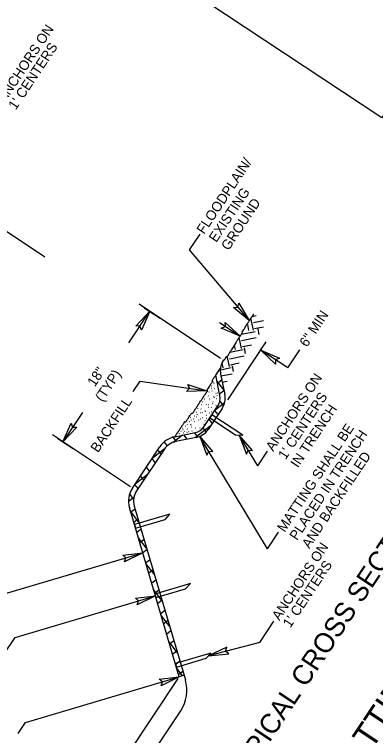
# Model space of a CAD drawing. Extents: x 561231 to 564240, y 590260 to 602519.
# Drawn here: x 563598.7 to 563838.5, y 590578.6 to 591057.7 of the extents above; entities that cross this region are included whole.
import ezdxf

# ---------------------------------------------------------------- set-up
doc = ezdxf.new("R2010")
doc.units = 0
doc.layers.add('Old_Level_1', color=7, linetype='Continuous')
doc.layers.add('Old_Level_2', color=7, linetype='Continuous')

# ---------------------------------------------------------------- blocks, each defined once
blk = doc.blocks.new('TERM')
at = {"layer": 'Old_Level_2'}
blk.add_lwpolyline([(-27, 4.65), (0, 0), (-27.15, -4.8), (-23.7, 0)], close=True, dxfattribs=at)

msp = doc.modelspace()

# ---------------------------------------------------------------- linework, layer by layer
at = {"layer": 'Old_Level_1'}
for p, q in [((563550.87, 590941.95), (563618.87, 590896.77)), ((563721.7, 590911.65), (563714.78, 590901.25)), ((563714.78, 590901.25), (563754.56, 590854.33)), ((563735.57, 590829.21), (563681.52, 590865.12)), ((563674.64, 590839.61), (563688.51, 590860.48)), ((563684.95, 590862.85), (563695.51, 590855.83)), ((563684.95, 590862.85), (563691.24, 590858.67)), ((563757.33, 590847.87), (563755.72, 590855.86)), ((563756.54, 590857.11), (563759.29, 590857.66)), ((563734.84, 590852.94), (563748.48, 590843.88)), ((563754.38, 590847.67), (563753.58, 590851.64)), ((563757.32, 590853.09), (563764.11, 590854.46)), ((563758.14, 590849.09), (563763.98, 590850.25)), ((563749.41, 590845.31), (563758.61, 590847.16)), ((563761.2, 590845.05), (563760.42, 590848.89)), ((563749.41, 590835.83), (563747.94, 590843.1)), ((563749.38, 590841.14), (563759.24, 590843.12)), ((563740.39, 590801.7), (563765.93, 590840.13)), ((563743.2, 590835.4), (563745.92, 590839.49)), ((563745.39, 590835.02), (563744.82, 590837.84)), ((563750.19, 590837.12), (563756.05, 590838.3)), ((563752.11, 590832.38), (563751.34, 590836.22)), ((563765.2, 590838.02), (563765.2, 590838.02)), ((563741.38, 590828.99), (563751.17, 590830.97)), ((563741.78, 590833.25), (563750.61, 590835.03)), ((563780.16, 590822.83), (563762.31, 590834.69)), ((563780.15, 590822.83), (563788.21, 590834.97)), ((563737.38, 590822.96), (563736.7, 590826.3)), ((563741.4, 590823.77), (563740.01, 590830.65)), ((563742.19, 590824.97), (563747.96, 590826.14)), ((563732.38, 590818.06), (563735.45, 590822.67)), ((563735.43, 590822.41), (563735.1, 590822.14)), ((563735.44, 590821.99), (563735.21, 590822.3)), ((563735.58, 590821.64), (563742.66, 590823.07)), ((563744.15, 590820.41), (563743.39, 590824.18)), ((563735.12, 590804.46), (563732.38, 590818.06)), ((563735.59, 590818.7), (563738.34, 590805.11)), ((563735.84, 590817.51), (563743.22, 590819)), ((563677.6, 590807.12), (563682.27, 590814.14)), ((563682.27, 590814.14), (563726.54, 590807.72)), ((563730.96, 590813.68), (563731.16, 590813.69)), ((563731.34, 590812.25), (563731.18, 590812.49)), ((563737.68, 590808.35), (563733.15, 590814.23)), ((563736.37, 590814.84), (563733.47, 590812.62)), ((563736.65, 590813.5), (563740.01, 590814.17)), ((563727.68, 590807.03), (563727.89, 590807.03)), ((563729.4, 590809.47), (563729.61, 590809.46)), ((563729.7, 590810.84), (563729.54, 590811.08)), ((563730.06, 590807.51), (563729.91, 590807.75)), ((563731.34, 590809.18), (563731.54, 590809.18)), ((563737.81, 590807.69), (563734.92, 590805.47)), ((563724.99, 590802.31), (563725.2, 590802.3)), ((563727.56, 590804.01), (563727.41, 590804.26)), ((563727.93, 590802.26), (563728.13, 590802.27)), ((563730.6, 590803.95), (563730.84, 590803.83)), ((563731.21, 590803.5), (563731.43, 590803.51)), ((563732.38, 590806.07), (563732.6, 590806.06)), ((563732.96, 590802.52), (563733.17, 590802.52)), ((563733.31, 590804.35), (563733.16, 590804.61)), ((563733.48, 590806.09), (563733.32, 590806.33)), ((563722.9, 590798.62), (563723.11, 590798.62)), ((563723.49, 590800.26), (563723.7, 590800.25)), ((563724.53, 590783.74), (563733.8, 590797.69)), ((563726.16, 590798.6), (563726.01, 590798.84)), ((563727.56, 590798.54), (563727.76, 590798.52)), ((563730.43, 590798.93), (563730.28, 590799.17)), ((563730.71, 590800.18), (563730.56, 590800.42)), ((563738.18, 590799.7), (563731.94, 590794.9)), ((563732.38, 590798.16), (563732.59, 590798.14)), ((563737.55, 590797.8), (563735.09, 590800.99)), ((563643.91, 590793.36), (563630.88, 590773.74)), ((563719.45, 590793.4), (563719.65, 590793.41)), ((563720.57, 590795.75), (563720.42, 590795.99)), ((563722.31, 590793.33), (563722.53, 590793.34)), ((563722.74, 590795.57), (563722.57, 590795.79)), ((563723.59, 590793.07), (563723.44, 590793.31)), ((563725.2, 590794.42), (563725.41, 590794.42)), ((563725.69, 590793.84), (563725.54, 590794.08)), ((563736.53, 590795.88), (563727.26, 590781.93)), ((563727.43, 590796.86), (563727.65, 590796.87)), ((563728.21, 590793.03), (563728.41, 590793.04)), ((563729.31, 590793.95), (563729.52, 590793.95)), ((563729.57, 590796.59), (563729.41, 590796.83)), ((563733.86, 590791.86), (563731.74, 590794.6)), ((563715.68, 590790.15), (563715.88, 590790.17)), ((563716.37, 590788.24), (563716.21, 590788.46)), ((563717.29, 590789.08), (563717.49, 590789.1)), ((563718.01, 590791.12), (563718.21, 590791.12)), ((563719.62, 590790.46), (563719.82, 590790.47)), ((563720.29, 590791.59), (563720.13, 590791.83)), ((563721.24, 590788.05), (563721.08, 590788.29)), ((563722.1, 590788.99), (563722.3, 590788.97)), ((563723.5, 590789.89), (563723.72, 590789.88)), ((563725.33, 590787.67), (563725.17, 590787.89)), ((563726.14, 590791.28), (563725.98, 590791.52)), ((563726.02, 590789.53), (563726.24, 590789.54)), ((563730.02, 590786.09), (563727.91, 590788.83)), ((563729.84, 590791.74), (563728.48, 590789.69)), ((563728.48, 590789.69), (563745.54, 590778.36)), ((563750.31, 590778.14), (563729.84, 590791.74)), ((563710.01, 590782.84), (563710.23, 590782.84)), ((563712.2, 590784.15), (563712.4, 590784.15)), ((563713.58, 590785.22), (563713.42, 590785.46)), ((563714.67, 590787.16), (563714.87, 590787.17)), ((563715.76, 590785.18), (563715.6, 590785.42)), ((563715.74, 590785.04), (563715.95, 590785.03)), ((563716.2, 590783.72), (563716.42, 590783.72)), ((563718.05, 590787.16), (563718.26, 590787.18)), ((563718.77, 590783.02), (563718.98, 590783.02)), ((563728.74, 590784.16), (563718.89, 590776.57)), ((563721.03, 590784.69), (563721.24, 590784.68)), ((563722.06, 590782.74), (563721.91, 590782.98)), ((563726.07, 590780.49), (563724.04, 590783.12)), ((563724.4, 590785.61), (563724.61, 590785.61)), ((563675.72, 590743.95), (563623.89, 590778.39)), ((563710.23, 590778.16), (563703.99, 590773.36)), ((563705.2, 590777.15), (563718.8, 590779.89)), ((563708.3, 590779.05), (563708.17, 590779.29)), ((563709.19, 590780.95), (563709.4, 590780.95)), ((563710.57, 590782.06), (563710.77, 590782.06)), ((563710.67, 590779.66), (563710.87, 590779.66)), ((563713.4, 590775.46), (563711.18, 590778.35)), ((563711.63, 590780.69), (563711.47, 590780.91)), ((563713.18, 590780.25), (563713.39, 590780.23)), ((563713.53, 590782.51), (563713.74, 590782.51)), ((563714.39, 590780.43), (563714.23, 590780.67)), ((563716.51, 590781.1), (563716.73, 590781.11)), ((563720.49, 590776.98), (563718.33, 590779.79)), ((563745.54, 590778.36), (563750.31, 590778.14)), ((563760.2, 590757.8), (563747.9, 590778.24)), ((563627.32, 590776.1), (563637.88, 590769.09)), ((563627.32, 590776.1), (563633.61, 590771.93)), ((563700.24, 590771.09), (563698.23, 590773.69)), ((563706.25, 590774.02), (563704.06, 590776.85)), ((563719.45, 590776.68), (563705.85, 590773.94)), ((563766.71, 590702.74), (563721.67, 590777.53)), ((563677.07, 590743.05), (563695.32, 590770.51)), ((563698.05, 590768.69), (563679.8, 590741.24)), ((563698.22, 590768.91), (563690.09, 590762.65)), ((563696.08, 590765.75), (563693.97, 590768.49)), ((563760.2, 590757.8), (563766.62, 590767.46)), ((563692.25, 590759.98), (563690.14, 590762.72)), ((563688.42, 590754.22), (563686.31, 590756.96)), ((563686.89, 590751.92), (563678.83, 590745.71)), ((563684.59, 590748.45), (563682.48, 590751.19)), ((563680.76, 590742.7), (563678.65, 590745.44)), ((563678, 590736.79), (563674.54, 590734.13)), ((563677.87, 590735.71), (563675.25, 590739.13)), ((563678.25, 590730.97), (563712.2, 590615.62)), ((563708.16, 590617.73), (563675.11, 590730.04)), ((563681.34, 590720.49), (563675.81, 590727.66)), ((563678.79, 590729.13), (563676.01, 590726.98)), ((563701.99, 590725.76), (563678.41, 590718.82)), ((563698.75, 590722.25), (563701.99, 590725.76)), ((563680.77, 590722.38), (563677.99, 590720.24)), ((563679.1, 590716.47), (563698.75, 590722.25)), ((563678.41, 590718.82), (563679.1, 590716.47)), ((563682.77, 590715.65), (563679.97, 590713.5)), ((563766.71, 590702.74), (563774.06, 590713.8)), ((563686.44, 590703.12), (563680.92, 590710.29)), ((563684.74, 590708.91), (563681.96, 590706.76)), ((563686.73, 590702.16), (563683.95, 590700.02)), ((563574.1, 590667.43), (563683.93, 590700.05)), ((563688.72, 590695.42), (563685.93, 590693.27)), ((563691.56, 590685.76), (563686.04, 590692.93)), ((563690.69, 590688.68), (563687.91, 590686.53)), ((563692.68, 590681.94), (563689.89, 590679.79)), ((563715.57, 590679.61), (563691.99, 590672.67)), ((563712.34, 590676.09), (563715.57, 590679.61)), ((563696.67, 590668.38), (563691.14, 590675.56)), ((563694.67, 590675.2), (563691.89, 590673.05)), ((563691.99, 590672.67), (563692.69, 590670.31)), ((563692.69, 590670.31), (563712.34, 590676.09)), ((563599.13, 590643.8), (563692.34, 590671.48)), ((563696.64, 590668.46), (563693.86, 590666.32)), ((563698.63, 590661.71), (563695.85, 590659.57)), ((563701.78, 590651.03), (563696.25, 590658.2)), ((563700.62, 590654.97), (563697.83, 590652.82)), ((563761.52, 590640.48), (563770.89, 590654.58)), ((563702.61, 590648.23), (563699.81, 590646.08)), ((563591.48, 590632.28), (563599.13, 590643.8)), ((563706.89, 590633.65), (563701.36, 590640.82)), ((563704.58, 590641.5), (563701.79, 590639.34)), ((563761.52, 590640.48), (563727.54, 590631.69)), ((563706.57, 590634.75), (563703.79, 590632.6)), ((563729.16, 590633.45), (563705.58, 590626.51)), ((563706.27, 590624.15), (563725.92, 590629.94)), ((563725.92, 590629.94), (563729.16, 590633.45)), ((563705.58, 590626.51), (563706.27, 590624.15)), ((563708.56, 590628), (563705.78, 590625.86)), ((563710.39, 590618.39), (563706.47, 590623.47)), ((563710.53, 590621.26), (563707.75, 590619.12)), ((563605.97, 590587.38), (563708.16, 590617.73)), ((563645.21, 590522.98), (563707.36, 590616.53)), ((563711.29, 590618.65), (563708.16, 590617.73)), ((563712, 590616.29), (563711.99, 590616.3)), ((563656.3, 590515.62), (563709.09, 590595.08)), ((563601.13, 590580.09), (563605.97, 590587.38))]:
    msp.add_line(p, q, dxfattribs=at)
for points in [[(563700.37, 591083.36), (563785.96, 591212.17), (563928.11, 591117.72), (563842.52, 590988.91)], [(563679.26, 590850.7), (563688.51, 590860.48), (563683.09, 590848.06), (563682.07, 590850.78)], [(563738.69, 590853.12), (563748.48, 590843.88), (563736.06, 590849.3), (563738.78, 590850.32)], [(563772.1, 590825.45), (563762.31, 590834.69), (563774.74, 590829.27), (563772.01, 590828.25)], [(563640.13, 590783.52), (563630.88, 590773.74), (563636.29, 590786.15), (563637.32, 590783.44)]]:
    msp.add_lwpolyline(points, close=True, dxfattribs=at)
for centre, radius, start, end in [((563748.61, 590820.78), 13.3, 147.4515, 171.833), ((563747.64, 590821.13), 12.29, 172.8174, 191.3993), ((563726.29, 590802.68), 9.01, 326.3993, 11.3993), ((563726.29, 590802.68), 12.29, 326.3993, 11.3993), ((563717.02, 590788.73), 9.01, 281.3993, 326.3993), ((563717.02, 590788.73), 12.29, 281.3993, 326.3993), ((563708.28, 590761.89), 15.57, 101.3993, 146.3993), ((563708.28, 590761.89), 12.29, 101.3993, 146.3993), ((563690.04, 590734.44), 15.57, 146.3993, 196.3993), ((563690.04, 590734.44), 12.29, 146.3993, 196.3993), ((563688.62, 590608.68), 24.58, 326.3993, 16.3993)]:
    msp.add_arc(centre, radius, start, end, dxfattribs=at)
for points in [[(563737.41, 590827.93), (563737.73, 590828.24), (563737.98, 590828.08), (563738.28, 590828.54), (563738.59, 590829), (563738.9, 590829.47), (563739.2, 590829.93), (563739.36, 590830.16), (563740.07, 590830.69), (563740.83, 590831.85), (563741.45, 590832.77), (563742.22, 590833.93), (563742.83, 590834.85), (563743.14, 590835.32), (563743.29, 590835.55), (563743.45, 590835.78), (563743.6, 590836.01), (563743.75, 590836.24), (563744.22, 590836.94), (563744.68, 590837.63), (563745.44, 590838.79), (563745.91, 590839.48), (563746.12, 590840.34), (563746.58, 590841.03), (563746.73, 590841.26), (563746.89, 590841.49), (563747.5, 590842.42), (563747.96, 590843.11), (563748.42, 590843.81), (563748.73, 590844.27), (563749.04, 590844.73), (563749.35, 590845.19), (563749.5, 590845.43), (563749.81, 590845.89), (563749.96, 590846.12), (563750.18, 590846.98), (563751.1, 590848.37), (563751.71, 590849.29), (563752.23, 590850.61), (563752.69, 590851.3), (563752.85, 590851.54), (563753.16, 590852), (563753.31, 590852.23), (563753.46, 590852.46), (563753.62, 590852.69), (563754.08, 590853.39), (563754.54, 590854.08), (563754.85, 590854.54), (563755.15, 590855.01), (563755.77, 590855.93), (563756.08, 590856.39), (563756.23, 590856.62), (563756.54, 590857.09), (563756.84, 590857.55), (563757.15, 590858.01), (563757.3, 590858.24), (563757.61, 590858.71)], [(563705.2, 590777.15), (563705.52, 590777.63), (563705.83, 590778.09), (563706.14, 590778.55), (563706.45, 590779.02), (563706.75, 590779.48), (563707.06, 590779.94), (563707.37, 590780.41), (563707.68, 590780.87), (563707.98, 590781.33), (563708.29, 590781.79), (563708.9, 590782.72), (563709.21, 590783.18), (563709.52, 590783.64), (563709.83, 590784.11), (563710.13, 590784.57), (563710.75, 590785.49), (563711.36, 590786.42), (563711.98, 590787.34), (563712.47, 590787.02), (563712.78, 590787.48), (563713.09, 590787.94), (563713.39, 590788.4), (563714.01, 590789.33), (563714.32, 590789.79), (563715.24, 590791.18), (563715.55, 590791.64), (563716.16, 590792.57), (563717.27, 590793.16), (563718.19, 590794.55), (563718.5, 590795.01), (563718.8, 590795.48), (563719.42, 590796.4), (563719.73, 590796.86), (563720.03, 590797.33), (563720.34, 590797.79), (563720.65, 590798.25), (563720.96, 590798.71), (563721.26, 590799.18), (563721.88, 590800.1), (563722.8, 590801.49), (563723.42, 590802.42), (563724.03, 590803.34), (563724.34, 590803.8), (563724.64, 590804.27), (563725.26, 590805.19), (563725.57, 590805.65), (563725.87, 590806.12), (563726.18, 590806.58), (563726.8, 590807.5), (563726.92, 590808.76), (563727.22, 590809.22), (563728.15, 590810.61), (563729.38, 590812.46), (563729.99, 590813.38), (563730.3, 590813.84), (563730.11, 590814.64), (563730.42, 590815.1), (563731.03, 590816.02), (563731.34, 590816.49), (563732.38, 590818.06)]]:
    msp.add_spline(points, degree=3, dxfattribs=at)

# ---------------------------------------------------------------- block references
for p, xscale, yscale, rotation in [((563754.55, 590854.34), 0.4913280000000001, 0.49132800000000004, -49.711969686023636), ((563726.55, 590807.72), 0.49132800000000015, 0.49132800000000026, -8.256239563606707), ((563721.69, 590777.54), 0.4913280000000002, -0.4913280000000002, 121.05520550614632), ((563747.92, 590778.25), 0.4913280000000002, -0.4913280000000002, 121.05520550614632), ((563683.94, 590700.06), 0.49132800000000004, 0.49132800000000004, 16.53992181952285), ((563692.35, 590671.49), 0.49132800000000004, 0.49132800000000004, 16.53992181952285), ((563727.54, 590631.69), 0.491328, -0.49132800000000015, -164.96308296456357), ((563708.17, 590617.74), 0.49132800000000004, 0.49132800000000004, 16.53992181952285)]:
    msp.add_blockref('TERM', p, dxfattribs=dict(at, xscale=xscale, yscale=yscale, rotation=rotation))

# ---------------------------------------------------------------- texts
for s, height, rotation, p in [('ANCHORS ON', 6.551, 56.3993, (563592.3, 590998.67)), ("1' CENTERS", 6.551, 56.3993, (563599.6, 590993.83)), ('FLOODPLAIN/', 6.5511, 56.3993, (563724.55, 590911.26)), ('EXISTING', 6.551, 56.3993, (563732.73, 590905.82)), ('GROUND', 6.551, 56.3993, (563740.92, 590900.38)), ('6" MIN', 6.551, 56.3993, (563792.89, 590836.22)), ('18"', 6.551, 56.3995, (563652.05, 590809.87)), ('(TYP)', 6.551, 56.3995, (563657.22, 590799.88)), ('ANCHORS ON', 6.551, 56.3993, (563770.52, 590766.96)), ("1' CENTERS", 6.551, 56.3993, (563778.71, 590761.52)), ('BACKFILL', 6.551, 56.3993, (563654.21, 590766.16)), ('IN TRENCH', 6.551, 56.3993, (563786.89, 590756.09)), ('MATTING SHALL BE', 6.5511, 56.3993, (563778.1, 590713.28)), ('PLACED IN TRENCH', 6.5511, 56.3993, (563786.28, 590707.85)), ('AND BACKFILLED', 6.5511, 56.3993, (563794.47, 590702.41)), ('TYPICAL CROSS SECTION', 13.102, 56.3993, (563749.01, 590545.12)), ('ANCHORS ON', 6.551, 56.3993, (563774.59, 590654.62)), ('COIR FIBER MATTING DETAIL', 16.3776, 56.3993, (563745.07, 590431.91)), ("1' CENTERS", 6.551, 56.3993, (563781.88, 590649.77))]:
    msp.add_text(s, height=height, rotation=rotation, dxfattribs=at).set_placement(p)

doc.saveas('drawing.dxf')
